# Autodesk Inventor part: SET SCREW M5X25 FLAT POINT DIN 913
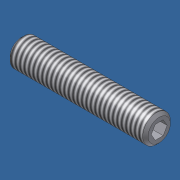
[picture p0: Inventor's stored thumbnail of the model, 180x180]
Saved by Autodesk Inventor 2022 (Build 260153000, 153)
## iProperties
Created: 2006-02
Part Number: SET SCREW M5X25 FLAT POINT DIN 913
Material: Steel, Mild
Description: Hexagon Socket Set Screw
Document SubType Name: Modeling
Standard: DIN 913
Designer: Andy Moles
Standards Organization: DIN
Language: en-US
Size Designation: M5 x 25
Categories: <MemberInstance><Categories><Category DisplayName="Fasteners" InternalName="e4da775c-781d-43d5-af7c-5136215cf5a6" Mnemonic="FSTN"><Category DisplayName="Bolts"
Density: 7.85 g/cm^3
Mass: 3.68426 g
Surface Area: 4.49764 cm^2
Volume: 0.469332 cm^3
Appearance: Zinc
Author: Andy Moles
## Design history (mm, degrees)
sketch "Sketch1"
  geometry: L1 (0, 0)-(21.167, 0); L2 (25, 1.443)-(25, 2.5); L3 (25, 2.5)-(0, 2.5); L4 (25, 1.443)-(22, 1.443); L5 (22, 1.443)-(21.167, 0); L6 (0, -0.25)-(0, 3.25) reference; L7 (0, 2.5)-(0, 0)
  constraints: 13 end point, 3 parallel, 1 collinear, 1 perpendicular, 1 point on line
  dimensions: "d0" = 3 distance of L2.start L4.end (= INTI); "d1" = 60 deg angle of L5 L1; "d2" = 5 diameter of L3 L1 (= NND); "d3" = 2.88675 diameter of L4 L1 (= 1.1547 x SW); "d5" = 25 distance from line of L2 L3.end (= NLG)
revolve "Body" sketch "Sketch1" stored, may be unused: angle "d6" = 90 deg
sketch "Sketch2"
  geometry: L1 (-0.722, 1.25)-(0.722, 1.25); L2 (0.722, 1.25)-(1.443, 0); L3 (1.443, 0)-(0.722, -1.25); L4 (0.722, -1.25)-(-0.722, -1.25); L5 (-0.722, -1.25)-(-1.443, 0); L6 (-1.443, 0)-(-0.722, 1.25); 3 further points
  constraints: 12 end point, 1 coincident, 1 horizontal, 13 other
extrude "Slot" join sketch "Sketch2" taper "d7" = 0 deg; stored distance "d21" = 10
workaxis "Work Axis1"
workplane "Work Plane1"
body "Solid1"
feature "Thread" dims "d8" = 25 (= NLG), "d9" = 0
chamfer "Chamfer1" distance "d10" = 0.49076 (= -0.5 x GD1 + 0.5 x NND); stored, may be unused: angle "d11" = 45 deg (= FAWI), second distance "d34" = 0.49076 (= -0.5 x GD1 + 0.5 x NND)
chamfer "Chamfer2" distance "d12" = 0.49076 (= -0.5 x GD1 + 0.5 x NND); stored, may be unused: angle "d13" = 45 deg (= FAWI), second distance "d35" = 0.49076 (= -0.5 x GD1 + 0.5 x NND)
other parameters: "NND" = 5 [user parameter; used in 5 equation terms], "NLG" = 25 [user parameter; used in 2 equation terms], "INTI" = 3 [user parameter; used in 1 equation term], "FAWI" = 45 deg [user parameter; used in 2 equation terms], "SW" = 2.5 [user parameter; used in 2 equation terms], "GD1" = 4.01848 (= THREADDIA - 1.2269 x PTC) [user parameter; used in 4 equation terms], "d4" = 0, "SPD" = 3.5 [user parameter], "d33" = 0, "d36" = 0, "GUL" = 0.49076 (= 0.61345 x PTC) [user parameter], "TPU" = 12.5 (computed from PTC) [user parameter], "TOA" = 30 deg [user parameter], "THREADDIA" = 5 [user parameter; used in 1 equation term], "PTC" = 0.8 [user parameter; used in 4 equation terms], "FAWI1" = 45 deg [user parameter], "GAL" = 0.49076 (= 0.61345 x PTC) [user parameter], "E0" = 2.8875 (= 1.155 x SW) [user parameter]
